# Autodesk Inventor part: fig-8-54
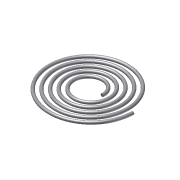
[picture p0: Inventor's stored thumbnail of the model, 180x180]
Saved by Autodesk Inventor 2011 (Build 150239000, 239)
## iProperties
Shininess: 77.0
Length Units: 11269
Angle Units: 11279
Time Units: 11290
Mass Units: 11283
Length Display Precision: 3
Angle Display Precision: 2
Created: 2002-01
Part Number: fig-8-54
Document SubType Name: Modeling
Designer: CADSoft
Density: 1 g/cm^3
Density: 0.0
Volumn: 0.0
Area: 0.0
PropertySet Name: Model Information
Control State: 0
Master: False
Checked Out: False
Author: CADSoft
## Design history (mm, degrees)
sketch "Sketch2"
  geometry: C1 r 2.5 at (-19.895, -0.092)
  constraints: 1 centre point
  dimensions: "d0" = 5 diameter of C1
coil "Coil5" sketch "Sketch2" pitch "d35" = 10; turns "d37" = 5; dims "d36" = 10, "d38" = 0, angle "d39" = 90 deg, angle "d40" = 90 deg, "d41" = 0, "d42" = 0
body "Solid1"
